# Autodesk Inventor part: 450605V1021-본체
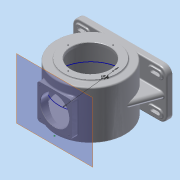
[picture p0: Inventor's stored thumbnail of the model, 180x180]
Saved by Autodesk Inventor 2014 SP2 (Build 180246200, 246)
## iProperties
Created: 2015-06
Part Number: 450605V1021-본체
Material: 알루미늄 6061
Document SubType Name: Modeling
Designer: 201-09
Mass: 3300.74 g
Surface Area: 2344.03 cm^2
Volume: 1217.99 cm^3
Density: 2.71 g/cm^3
Appearance: 알루미늄 - 평지
Author: 201-09
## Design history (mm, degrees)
sketch "스케치1"
  geometry: C1 r 85 at (0, 0); 1 further point
  constraints: 1 centre point, 1 coincident
  dimensions: "d0" = 170 diameter of C1
extrude "돌출1" new body sketch "스케치1" distance "d1" = 118; taper "d2" = 0 deg
sketch "스케치2"
  geometry: C1 r 65 at (0, 0); 1 further point
  constraints: 1 centre point, 1 coincident
  dimensions: "d3" = 130 diameter of C1
extrude "돌출2" join sketch "스케치2" distance "d4" = 13; taper "d5" = 0 deg
sketch "스케치3"
  geometry: C1 r 65 at (0, 0); 1 further point
  constraints: 1 centre point, 1 coincident
  dimensions: "d6" = 130 diameter of C1
extrude "돌출3" join sketch "스케치3" distance "d7" = 3; taper "d8" = 0 deg
sketch "스케치4"
  geometry: C1 r 47.5 at (0, 0); 1 further point
  constraints: 1 centre point, 1 coincident
  dimensions: "d9" = 95 diameter of C1
extrude "돌출4" cut sketch "스케치4" distance "d10" = 7; taper "d11" = 0 deg
sketch "스케치5"
  geometry: C1 r 77 at (0, 0); 1 further point
  constraints: 1 centre point, 1 coincident
  dimensions: "d12" = 154 diameter of C1
node "작업 평면6"
sketch "스케치6"
  geometry: C1 r 31 at (0, 0); 1 further point
  constraints: 1 centre point, 1 coincident
  dimensions: "d15" = 62 diameter of C1
extrude "돌출6" join sketch "스케치6" distance "d16" = 3.5; taper "d17" = -15 deg
node "작업 평면7"
sketch "스케치7"
  geometry: C1 r 23.5 at (0, 0); 1 further point
  constraints: 1 centre point, 1 coincident
  dimensions: "d18" = 47 diameter of C1
extrude "돌출7" cut sketch "스케치7" distance "d19" = 14; taper "d20" = 0 deg
node "작업 평면1"
sketch "스케치9"
  geometry: L1 (85, 118)-(-85, 118) reference; L2 (-85, 0)-(85, 0) reference; L3 (65, 121)-(-65, 121) reference; L4 (-65, -13)-(65, -13) reference; L5 (0, -13)-(0, 121); C1 r 42.5 at (0, 54); 1 further point
  constraints: 3 midpoint, 2 end point, 1 centre point
  dimensions: "d25" = 85 diameter of C1
extrude "돌출9" join sketch "스케치9" stored distance "d26" = 3; taper "d27" = 0 deg
sketch "스케치10"
  geometry: C1 r 42.5 at (0, 0) reference; C2 r 35 at (0, 0); 1 further point
  constraints: 1 centre point, 1 coincident
  dimensions: "d28" = 70 diameter of C2
  node "투영된 루프2"
node "작업 평면2"
sketch "스케치11"
  geometry: L1 (-85, 0)-(85, 0) reference; L2 (85, 118)-(-85, 118) reference; L3 (-65, -13)-(65, -13) reference; L4 (65, 0)-(-65, 0) reference; L5 (65, 121)-(-65, 121) reference; L6 (115, 59)-(115, 118); L7 (115, 118)-(-115, 118); L8 (-115, 118)-(-115, 0); L9 (-115, 0)-(115, 0); L10 (115, 0)-(115, 59); 3 further points
  constraints: 10 end point, 2 midpoint, 1 collinear, 1 parallel, 1 perpendicular, 1 other
  dimensions: "d33" = 59 distance of L6.start L6.end; "d35" = 230 distance of L6.end L7.end; "d36" = 118 distance of L7.end L8.end; "d37" = 230 distance of L8.end L9.end
extrude "돌출11" join sketch "스케치11" distance "d38" = 14; taper "d39" = 0 deg
node "작업 평면3"
sketch "스케치12"
  geometry: L1 (46.733, 71)-(115, 71) reference; L2 (-115, 71)-(-46.733, 71) reference; L3 (-115, 71)-(-109, 71); L4 (-109, 71)-(-84.87, 4.703); L5 (0, 0)-(0, 84.436); L6 (115, 71)-(46.733, 71); L7 (115, 71)-(109, 71); L8 (109, 71)-(84.87, 4.703); A1 r 85 centre (0, 0) between (-46.733, 71) and (46.733, 71) reference; A2 r 85 centre (0, 0) between (-46.733, 71) and (46.733, 71); 1 further point
  constraints: 12 end point, 4 point on circle, 4 symmetric about line, 2 point on line, 1 centre point, 1 perpendicular, 1 other
  dimensions: "d40" = 6 distance of L2.start L3.end; "d41" = 110 deg angle of L3 L4
extrude "돌출12" join sketch "스케치12" stored distance "d42" = 15; taper "d43" = 0 deg
fillet "모깎기1" dims "d45" = 18
sketch "스케치14"
  geometry: L1 (-115, 100)-(-115, 18) reference; L2 (-97, 0)-(-46.733, 0) reference; L3 (-46.733, 51.5)-(-46.733, 0) reference; L4 (-46.733, 51.5)-(-109, 51.5) reference; L5 (-109, 51.5)-(-109, 66.5) reference; L6 (-109, 66.5)-(-46.733, 66.5) reference; L7 (-46.733, 118)-(-46.733, 66.5) reference; L8 (-46.733, 118)-(-97, 118) reference; L9 (97, 118)-(46.733, 118) reference; L10 (46.733, 66.5)-(46.733, 118) reference; L11 (46.733, 66.5)-(109, 66.5) reference; L12 (109, 66.5)-(109, 51.5) reference; L13 (109, 51.5)-(46.733, 51.5) reference; L14 (46.733, 0)-(46.733, 51.5) reference; L15 (46.733, 0)-(97, 0) reference; L16 (115, 18)-(115, 100) reference; L17 (46.733, 51.5)-(84.87, 51.5) reference; L18 (84.87, 51.5)-(84.87, 66.5) reference; L19 (84.87, 66.5)-(46.733, 66.5) reference; L20 (46.733, 66.5)-(46.733, 118) reference; L21 (-46.733, 118)-(46.733, 118) reference; L22 (-46.733, 118)-(-46.733, 66.5) reference; L23 (-46.733, 66.5)-(-84.87, 66.5) reference; L24 (-84.87, 66.5)-(-84.87, 51.5) reference; L25 (-84.87, 51.5)-(-46.733, 51.5) reference; L26 (-46.733, 51.5)-(-46.733, 0) reference; L27 (46.733, 0)-(-46.733, 0) reference; L28 (46.733, 0)-(46.733, 51.5) reference; L29 (-97, 109)-(-81, 109); L30 (-81, 104)-(-97, 104); L31 (-97, 96)-(-81, 96); L32 (-81, 91)-(-97, 91); L33 (0, 118)-(0, 0); L34 (97, 96)-(81, 96); L35 (81, 91)-(97, 91); L36 (97, 109)-(81, 109); L37 (81, 104)-(97, 104); L38 (-115, 59)-(115, 59); L39 (97, 0)-(46.733, 0); L40 (-46.733, 0)-(46.733, 0); L41 (-46.733, 0)-(-97, 0); L42 (97, 22)-(81, 22); L43 (81, 27)-(97, 27); L44 (81, 14)-(97, 14); L45 (97, 9)-(81, 9); L46 (-97, 9)-(-81, 9); L47 (-81, 14)-(-97, 14); L48 (-81, 27)-(-97, 27); L49 (-97, 22)-(-81, 22); A1 r 18 centre (-97, 100) between (-97, 118) and (-115, 100) reference; A2 r 18 centre (-97, 18) between (-115, 18) and (-97, 0) reference; A3 r 18 centre (97, 100) between (115, 100) and (97, 118) reference; A4 r 18 centre (97, 18) between (97, 0) and (115, 18) reference; A5 r 4 centre (-97, 100) between (-97, 104) and (-97, 96); A6 r 4 centre (-81, 100) between (-81, 96) and (-81, 104); A7 r 9 centre (-97, 100) between (-89, 95.877) and (-88.938, 96); A8 r 9 centre (-81, 100) between (-89.062, 96) and (-89, 95.877); A9 r 9 centre (-81, 100) between (-81, 91) and (-81, 109); A10 r 9 centre (-81, 100) between (-89, 104.123) and (-89.062, 104); A11 r 9 centre (-97, 100) between (-88.938, 104) and (-89, 104.123); A12 r 9 centre (-97, 100) between (-97, 109) and (-97, 91); A13 r 9 centre (81, 100) between (81, 109) and (81, 91); A14 r 4 centre (81, 100) between (81, 104) and (81, 96); A15 r 9 centre (97, 100) between (89, 104.123) and (88.938, 104); A16 r 9 centre (97, 100) between (88.938, 96) and (89, 95.877); A17 r 9 centre (81, 100) between (89.062, 104) and (89, 104.123); A18 r 9 centre (81, 100) between (89, 95.877) and (89.062, 96); A19 r 4 centre (97, 100) between (97, 96) and (97, 104); A20 r 9 centre (97, 100) between (97, 91) and (97, 109); A21 r 4 centre (81, 18) between (81, 22) and (81, 14); A22 r 9 centre (81, 18) between (81, 27) and (81, 9); A23 r 18 centre (-97, 18) between (-115, 18) and (-97, 0); A24 r 9 centre (-81, 18) between (-81, 9) and (-81, 27); A25 r 4 centre (-81, 18) between (-81, 14) and (-81, 22); A26 r 4 centre (-97, 18) between (-97, 22) and (-97, 14); A27 r 9 centre (-97, 18) between (-97, 27) and (-97, 9); A28 r 18 centre (97, 18) between (97, 0) and (115, 18); A29 r 9 centre (97, 18) between (89, 22.123) and (88.938, 22); A30 r 9 centre (81, 18) between (89.062, 22) and (89, 22.123); A31 r 4 centre (97, 18) between (97, 14) and (97, 22); A32 r 9 centre (81, 18) between (89, 13.877) and (89.062, 14); A33 r 9 centre (97, 18) between (88.938, 14) and (89, 13.877); A34 r 9 centre (97, 18) between (97, 9) and (97, 27); A35 r 9 centre (-97, 18) between (-89, 13.877) and (-88.938, 14); A36 r 9 centre (-97, 18) between (-88.938, 22) and (-89, 22.123); A37 r 9 centre (-81, 18) between (-89, 22.123) and (-89.062, 22); A38 r 9 centre (-81, 18) between (-89.062, 14) and (-89, 13.877); 3 further points
  constraints: 68 point on circle, 62 symmetric about line, 42 end point, 34 centre point, 16 point on line, 12 coincident, 6 tangent, 3 midpoint, 1 perpendicular, 27 other
extrude "돌출13" join sketch "스케치14" distance "d51" = 3; taper "d52" = 0 deg
sketch "스케치15"
  geometry: L1 (-97, 96)-(-89.062, 96) reference; L2 (-88.938, 96)-(-81, 96) reference; L3 (-81, 104)-(-88.938, 104) reference; L4 (-89.062, 104)-(-97, 104) reference; L5 (-97, 14)-(-89.062, 14) reference; L6 (-88.938, 14)-(-81, 14) reference; L7 (-81, 22)-(-88.938, 22) reference; L8 (-89.062, 22)-(-97, 22) reference; L9 (81, 14)-(88.938, 14) reference; L10 (89.062, 14)-(97, 14) reference; L11 (97, 22)-(89.062, 22) reference; L12 (88.938, 22)-(81, 22) reference; L13 (97, 104)-(89.062, 104) reference; L14 (88.938, 104)-(81, 104) reference; L15 (81, 96)-(88.938, 96) reference; L16 (89.062, 96)-(97, 96) reference; A1 r 4 centre (-97, 100) between (-97, 104) and (-97, 96) reference; A2 r 9 centre (-81, 100) between (-89.062, 96) and (-89, 95.877) reference; A3 r 9 centre (-97, 100) between (-89, 95.877) and (-88.938, 96) reference; A4 r 4 centre (-81, 100) between (-81, 96) and (-81, 104) reference; A5 r 9 centre (-97, 100) between (-88.938, 104) and (-89, 104.123) reference; A6 r 9 centre (-81, 100) between (-89, 104.123) and (-89.062, 104) reference; A7 r 9 centre (-81, 18) between (-89.062, 14) and (-89, 13.877) reference; A8 r 9 centre (-97, 18) between (-89, 13.877) and (-88.938, 14) reference; A9 r 4 centre (-81, 18) between (-81, 14) and (-81, 22) reference; A10 r 9 centre (-97, 18) between (-88.938, 22) and (-89, 22.123) reference; A11 r 9 centre (-81, 18) between (-89, 22.123) and (-89.062, 22) reference; A12 r 4 centre (-97, 18) between (-97, 22) and (-97, 14) reference; A13 r 9 centre (97, 18) between (88.938, 14) and (89, 13.877) reference; A14 r 9 centre (81, 18) between (89, 13.877) and (89.062, 14) reference; A15 r 4 centre (97, 18) between (97, 14) and (97, 22) reference; A16 r 9 centre (81, 18) between (89.062, 22) and (89, 22.123) reference; A17 r 9 centre (97, 18) between (89, 22.123) and (88.938, 22) reference; A18 r 4 centre (81, 18) between (81, 22) and (81, 14) reference; A19 r 9 centre (81, 100) between (89.062, 104) and (89, 104.123) reference; A20 r 9 centre (97, 100) between (89, 104.123) and (88.938, 104) reference; A21 r 4 centre (81, 100) between (81, 104) and (81, 96) reference; A22 r 9 centre (97, 100) between (88.938, 96) and (89, 95.877) reference; A23 r 9 centre (81, 100) between (89, 95.877) and (89.062, 96) reference; A24 r 4 centre (97, 100) between (97, 96) and (97, 104) reference; 1 further point
extrude "돌출14" cut sketch "스케치15" stored distance "d53" = 3; taper "d54" = 0 deg
sketch "스케치16"
  geometry: L1 (-42.5, 54)-(-42.5, 96.5); L2 (-42.5, 96.5)-(42.5, 96.5); L3 (42.5, 96.5)-(42.5, 11.5); L4 (42.5, 11.5)-(-42.5, 11.5); L5 (-42.5, 11.5)-(-42.5, 54); 2 further points
  constraints: 10 end point, 2 parallel, 2 vertical, 1 horizontal alignment, 1 perpendicular, 1 other
  dimensions: "d55" = 42.5 distance of L1.start L1.end; "d56" = 85 distance of L1.end L2.end; "d57" = 85 distance of L2.end L3.end; "d58" = 85 distance of L3.end L4.end
extrude "돌출15" join sketch "스케치16" stored distance "d59" = 3; taper "d60" = 0 deg
sketch "스케치17"
  geometry: 1 further point
extrude "돌출16" cut sketch "스케치10" stored distance "d61" = 3; taper "d62" = 0 deg
node "작업 평면9"
sketch "스케치19"
  geometry: C1 r 65 at (0, 0) reference; C2 r 77 at (0, 0); 1 further point
  constraints: 1 centre point, 1 coincident
  dimensions: "d64" = 154 diameter of C2
extrude "돌출17" cut sketch "스케치19" distance "d65" = 102; taper "d66" = 0 deg
sketch "스케치20"
  geometry: L1 (42.5, 11.5)-(42.5, 96.5) reference; L2 (42.5, 96.5)-(-42.5, 96.5) reference; L3 (-42.5, 96.5)-(-42.5, 11.5) reference; L4 (-42.5, 11.5)-(42.5, 11.5) reference; L5 (0, 54)-(0, 89.5); L6 (0, 89.5)-(35.5, 89.5); L7 (35.5, 89.5)-(35.5, 18.5); L8 (35.5, 18.5)-(-35.5, 18.5); L9 (-35.5, 18.5)-(-35.5, 89.5); L10 (-35.5, 89.5)-(0, 89.5); 5 further points
  constraints: 12 end point, 4 coincident, 3 perpendicular, 2 parallel
  dimensions: "d67" = 35.5 distance of L5.start L5.end; "d68" = 35.5 distance of L5.end L6.end; "d69" = 71 distance of L6.end L7.end; "d70" = 71 distance of L7.end L8.end; "d71" = 71 distance of L8.end L9.end
hole "구멍1" sketch "스케치20" at (35.5, 89.5), (-35.5, 89.5), (-35.5, 18.5), (35.5, 18.5) diameter "d72" = 3.242; stored, may be unused: countersink angle "d76" = 90 deg, drill point angle "d78" = 118 deg; dims "d73" = 10, "d74" = 4, "d75" = 2, "d77" = 13
sketch "스케치21"
  geometry: A1 r 55 centre (0, 0) between (0, -55) and (0, 55); 3 further points
  constraints: 4 point on circle, 1 centre point, 1 coincident
  dimensions: "d79" = 110 diameter of A1
hole "구멍2" sketch "스케치21" at (0, -55), (55, 0), (0, 55), (-55, 0) diameter "d80" = 3.242; stored, may be unused: countersink angle "d84" = 90 deg, drill point angle "d86" = 118 deg; dims "d81" = 13, "d82" = 4, "d83" = 2, "d85" = 13
sketch "스케치24"
  geometry: L1 (0, 0)-(-92.569, -43.166); L2 (0, 0)-(102.138, 0); L3 (-92.569, -43.166)-(-54.707, -124.362); L4 (-92.569, -43.166)-(-119.811, 15.256)
  constraints: 8 end point, 1 collinear, 1 equal length, 1 horizontal, 1 perpendicular
  dimensions: "d87" = 155 deg angle of L1 L2
node "작업 평면4"
sketch "스케치25"
  geometry: L1 (0, 121)-(-43.166, 121) reference; L2 (-43.166, 121)-(-43.166, -14.256); 1 further point
  constraints: 2 end point, 1 perpendicular
node "작업 평면5"
sketch "스케치26"
  geometry: L1 (0, 1.158)-(134, 1.158); L2 (134, -64.02)-(134, 65.98) reference; 2 further points
  constraints: 2 end point, 2 horizontal, 1 midpoint
feature "엠보싱1" sketch "스케치26" dims "d90" = 0.5, "d91" = 0
fillet "모깎기2" dims "d92" = 3
fillet "모깎기3" dims "d93" = 3
fillet "모깎기6" dims "d96" = 3
chamfer "모따기1" distance "d98" = 1; stored, may be unused: second distance "d99" = 2, angle "d100" = 45 deg
fillet "모깎기9" dims "d102" = 7
fillet "모깎기10" dims "d103" = 3
fillet "모깎기11" dims "d104" = 7.5
fillet "모깎기12" dims "d105" = 3
sketch "스케치27"
  geometry: C1 r 77 at (0, 0); 1 further point
  constraints: 1 centre point, 1 coincident
  dimensions: "d106" = 154 diameter of C1
node "작업 평면10"
sketch "스케치29"
  geometry: C1 r 47.5 at (0, 0); 1 further point
  constraints: 1 centre point, 1 coincident
  dimensions: "d108" = 95 diameter of C1
extrude "돌출18" join sketch "스케치29" stored distance "d109" = 11; taper "d110" = 0 deg
sketch "스케치30"
  geometry: C1 r 47.5 at (0, 0); 1 further point
  constraints: 1 centre point, 1 coincident
  dimensions: "d111" = 95 diameter of C1
extrude "돌출19" cut sketch "스케치30" distance "d112" = 11; taper "d113" = 0 deg
extrude "돌출24" cut sketch "스케치5" distance "d132" = 102; taper "d133" = 0 deg
sketch "스케치36"
  geometry: C1 r 31 at (0, 0); 1 further point
  constraints: 1 centre point, 1 coincident
  dimensions: "d137" = 62 diameter of C1
extrude "돌출26" join sketch "스케치36" distance "d138" = 3.5; taper "d139" = 0 deg
sketch "스케치37"
  geometry: C1 r 23.5 at (0, 0); 1 further point
  constraints: 1 centre point, 1 coincident
  dimensions: "d140" = 47 diameter of C1
extrude "돌출27" cut sketch "스케치37" distance "d141" = 14; taper "d142" = 0 deg
sketch "스케치38"
  geometry: C1 r 15 at (0, 0); 1 further point
  constraints: 1 centre point, 1 coincident
  dimensions: "d143" = 30 diameter of C1
extrude "돌출28" cut sketch "스케치38" distance "d144" = 3; taper "d145" = 0 deg
fillet "모깎기16" dims "d146" = 3
fillet "모깎기17" dims "d147" = 0.3
chamfer "모따기3" distance "d148" = 1; stored, may be unused: second distance "d149" = 2, angle "d150" = 45 deg
sketch "스케치39"
  geometry: L1 (35.5, 96.5)-(0, 96.5) reference; L2 (0, 96.5)-(-35.5, 96.5) reference; L3 (-42.5, 89.5)-(-42.5, 18.5) reference; L4 (-35.5, 11.5)-(0, 11.5) reference; L5 (0, 11.5)-(35.5, 11.5) reference; L6 (42.5, 18.5)-(42.5, 89.5) reference; C1 r 1.621 at (-35.5, 18.5) reference; C2 r 1.621 at (35.5, 89.5) reference; C3 r 1.621 at (-35.5, 89.5) reference; C4 r 1.621 at (35.5, 18.5) reference; C5 r 35 at (0, 54); A1 r 7 centre (35.5, 89.5) between (42.5, 89.5) and (35.5, 96.5) reference; A2 r 7 centre (-35.5, 89.5) between (-35.5, 96.5) and (-42.5, 89.5) reference; A3 r 7 centre (-35.5, 18.5) between (-42.5, 18.5) and (-35.5, 11.5) reference; A4 r 7 centre (35.5, 18.5) between (35.5, 11.5) and (42.5, 18.5) reference; 1 further point
  constraints: 1 centre point
  dimensions: "d151" = 70 diameter of C5
extrude "돌출29" cut sketch "스케치39" stored distance "d152" = 3; taper "d153" = 0 deg
chamfer "모따기4" distance "d154" = 1; stored, may be unused: second distance "d155" = 2, angle "d156" = 45 deg
fillet "모깎기18" dims "d163" = 3
node "솔리드1"
node "투영된 루프1"
node "투영된 루프3"
node "투영된 루프4"
node "투영된 루프8"
node "투영된 루프9"
node "투영된 루프10"
node "투영된 루프11"
node "투영된 루프12"
node "투영된 루프13"
node "투영된 루프14"
node "투영된 루프15"
node "투영된 루프17"
node "투영된 루프18"
node "투영된 루프19"
other parameters: "d24" = -88, "d31" = 85, "d49" = 18, "d88" = -90.25, "d89" = -25 deg
